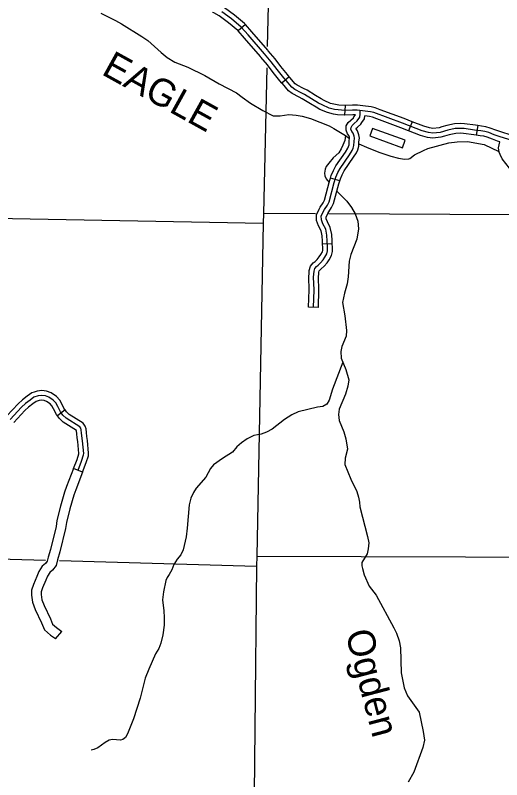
# Model space of a CAD drawing. Extents: x 0 to 3171, y 0 to 2059.
# Drawn here: x 1872.3 to 1997.6, y 790.8 to 987.9 of the extents above; entities that cross this region are included whole.
import ezdxf

# ---------------------------------------------------------------- set-up
doc = ezdxf.new("R2010")
doc.units = 0
for name, color, linetype in [('Level 35', 7, 'Continuous'), ('Level 4', 7, 'Continuous'), ('Level 45', 7, 'Continuous'), ('Level 46', 7, 'Continuous'), ('Level 5', 7, 'Continuous'), ('Level 57', 7, 'Continuous')]:
    doc.layers.add(name, color=color, linetype=linetype)

msp = doc.modelspace()

# ---------------------------------------------------------------- linework, layer by layer
at = {"layer": 'Level 35'}
for points in [[(1894.33, 988.4), (1896.9, 987.1), (1898.11, 986.49), (1899.61, 985.66), (1904.88, 982.36), (1906.38, 981.32), (1909.83, 978.25), (1911.4, 976.96), (1913.33, 975.73), (1916.74, 974.52), (1921.1, 972.37), (1924.81, 970.17), (1929.25, 967.85), (1930.73, 966.74), (1932.84, 965.18), (1936.01, 963.35), (1938.72, 961.93), (1940.55, 961.96), (1942.77, 962.31), (1944.67, 962.11), (1946.15, 961.83), (1948.35, 961.25), (1953.12, 959.36), (1954.34, 958.66), (1957.38, 956.88), (1958.4, 956.13)], [(1957.38, 956.88), (1957.2, 955.6), (1956.69, 954.35), (1956.25, 953.43), (1955.6, 952.43), (1954.12, 951.11), (1953.04, 949.77), (1952.4, 948.89), (1952.08, 948.21), (1951.91, 947.2), (1952, 946.51), (1952.38, 945.68), (1953.16, 944.74)], [(1960.78, 954.74), (1962.74, 953.85), (1965.9, 952.59), (1969.05, 951.58), (1971, 951.03), (1972.57, 950.73), (1973.63, 950.81)], [(1973.63, 950.81), (1973.9, 950.98), (1975.08, 951.9), (1977.46, 953.01), (1978.54, 953.5), (1983.96, 954.95), (1986.13, 955.25), (1988.75, 955.31), (1993.08, 954.52), (1996.88, 952.73)], [(1955.15, 942.53), (1957.71, 939.96), (1958.9, 938.3), (1959.8, 936.7), (1960.48, 934.79), (1960.67, 932.8), (1960.29, 930.18), (1958.74, 926.2), (1958.32, 924.5), (1958.04, 920.47), (1957.77, 918.6), (1957.11, 916.21), (1956.59, 913.78), (1957.17, 910.4), (1957.62, 906.63), (1957.47, 905.18), (1956.43, 902.51), (1956.15, 901.21), (1956.24, 899.44), (1957.44, 896.53), (1958.21, 893.89), (1957.95, 892.24), (1957.31, 890.21), (1955.72, 886.35)], [(1956.62, 898.45), (1954.01, 891.45), (1953.16, 888.61), (1952.51, 887.65), (1951.48, 887.05), (1950.12, 886.82), (1945.17, 885.61), (1943.51, 884.9), (1941.64, 883.68), (1938.49, 881.2), (1937.02, 880.44), (1935.58, 879.92), (1933.76, 879.56), (1931.98, 878.67), (1930.51, 877.64), (1929.35, 876.59), (1928.25, 875.27)], [(1955.72, 886.35), (1955.54, 884.96), (1955.74, 883.41), (1956.91, 880.51), (1957.42, 878.71), (1957.85, 875.98)], [(1928.25, 875.27), (1925.64, 873.6), (1923.3, 871.96), (1922.58, 871.05), (1921.36, 868.81), (1918.88, 865.96), (1918.16, 864.81), (1917.51, 863.35), (1917.07, 861.66), (1916.56, 855.66), (1916.29, 853.39), (1915.53, 850.1), (1914.89, 848.82), (1913.99, 847.65), (1913.09, 846.27), (1912.56, 844.9), (1911.92, 843.68), (1911.38, 842.97), (1911.03, 842.13), (1910.43, 839.21), (1910.18, 837.17), (1910.55, 834.34), (1910.66, 832.66), (1910.63, 830.61), (1910.25, 828.17), (1909.75, 826), (1909.29, 824.6), (1908.4, 823.22), (1906.64, 819.27), (1905.75, 816.96), (1904.44, 811.86), (1902.72, 806.55), (1901.17, 802.65), (1900.63, 801.71), (1899.97, 801.15), (1899.41, 801.01), (1897.3, 801.16), (1896.48, 801.03), (1895.43, 800.42), (1893.53, 799.05), (1892.54, 798.61), (1891.86, 798.44)], [(1957.85, 875.98), (1957.24, 873.71), (1957.2, 872.09), (1958.74, 868.3), (1960.25, 865.14), (1960.7, 863.66), (1960.98, 862.34), (1961.06, 861.13), (1963.04, 853.51), (1963.33, 851.87), (1963.21, 850.33), (1962.91, 849.03), (1961.55, 846.78), (1961.55, 845.95), (1961.69, 845.23), (1962.17, 843.62), (1963.44, 840.73), (1965.25, 838.35), (1969.8, 830), (1970.5, 828.59), (1971.2, 826.65), (1971.48, 824.82), (1971.65, 818.35), (1972.44, 814.52), (1973.29, 812.42), (1976.31, 808.2), (1977.39, 803.26), (1977.73, 801.03), (1977.28, 799.12), (1974.94, 792.73), (1973.46, 790.22)]]:
    msp.add_lwpolyline(points, dxfattribs=at)
at = {"layer": 'Level 4'}
for points in [[(1940.08, 1108.86), (1938.25, 1024.59), (1938.2, 1022.15), (1937.2, 979.77)], [(1937.07, 974.28), (1936.19, 936.73), (1936.13, 934.31), (1934.5, 848.41), (1934.45, 845.84), (1933.54, 762.01), (1933.51, 759.63), (1932.18, 672.84), (1931.53, 633.35)]]:
    msp.add_lwpolyline(points, dxfattribs=at)
at = {"layer": 'Level 45'}
for p, q in [((1931.54, 985.49), (1929.66, 983.84)), ((1942.85, 972), (1940.96, 970.37)), ((1957.24, 964.58), (1957.07, 962.08)), ((1974.51, 960.42), (1973.61, 958.09)), ((1991.39, 959.43), (1990.99, 956.96)), ((1955.88, 945.17), (1953.49, 945.88)), ((1953.92, 928.98), (1951.42, 928.87)), ((1950.35, 912.51), (1947.85, 912.59)), ((1885.09, 886.14), (1883.13, 884.59)), ((1889.6, 870.12), (1887.27, 871.04))]:
    msp.add_line(p, q, dxfattribs=at)
for points in [[(1931.54, 985.49), (1931.35, 985.7), (1928.77, 987.9), (1926.16, 989.76), (1924.48, 990.76), (1923.86, 990.96)], [(1929.66, 983.84), (1929.6, 983.91), (1927.23, 985.92), (1924.79, 987.67), (1923.45, 988.47), (1923.11, 988.58)], [(2001.9, 955.03), (1996.93, 956.59), (1995.65, 957.08), (1994.25, 957.61), (1993.27, 957.88), (1992.19, 958.03), (1990.61, 958.28), (1987.91, 958.63), (1986.86, 958.71), (1985.58, 958.63), (1983.74, 958.23), (1981.69, 957.64), (1979.83, 957.46), (1978.73, 957.61), (1977.1, 958.08), (1972.01, 960.04), (1964.62, 962.8), (1963.74, 963.01), (1961.69, 963.25), (1960.34, 963.42), (1959.18, 963.43), (1957.2, 963.33), (1955.45, 963.45), (1954.5, 963.6), (1953.09, 963.95), (1951.31, 964.73), (1950.41, 965.23), (1946.81, 967.43), (1945.95, 967.88), (1944.27, 968.74), (1943.49, 969.29), (1942.03, 971.04), (1941.42, 971.75), (1939.72, 973.9), (1938.23, 975.88), (1936.5, 977.9), (1932.23, 982.81), (1930.48, 984.8), (1928, 986.91), (1925.48, 988.71)], [(1937.33, 978.86), (1933.17, 983.63), (1931.54, 985.49)], [(1935.44, 977.22), (1931.29, 981.98), (1929.66, 983.84)], [(1942.85, 972), (1942.38, 972.55), (1940.71, 974.67), (1939.21, 976.66), (1937.45, 978.71), (1937.33, 978.86)], [(1940.96, 970.37), (1940.45, 970.96), (1938.73, 973.14), (1937.26, 975.1), (1935.56, 977.08), (1935.44, 977.22)], [(1949.6, 967.18), (1947.43, 968.51), (1946.52, 968.99), (1944.92, 969.81), (1944.35, 970.21), (1942.98, 971.85), (1942.85, 972)], [(1948.3, 965.05), (1946.19, 966.34), (1945.37, 966.77), (1943.62, 967.66), (1942.64, 968.36), (1941.07, 970.23), (1940.96, 970.37)], [(1957.24, 964.58), (1955.59, 964.7), (1954.75, 964.83), (1953.5, 965.14), (1951.86, 965.85), (1951.04, 966.31), (1949.6, 967.18)], [(1957.07, 962.08), (1955.31, 962.21), (1954.25, 962.38), (1952.69, 962.77), (1950.76, 963.6), (1949.78, 964.15), (1948.3, 965.05)], [(1966.26, 963.52), (1964.98, 964), (1963.96, 964.24), (1961.84, 964.49), (1960.42, 964.67), (1959.15, 964.68), (1957.22, 964.58), (1957.24, 964.58)], [(1974.51, 960.42), (1972.45, 961.21), (1966.26, 963.52)], [(1949.1, 912.55), (1949.26, 917.12), (1949.13, 920.37), (1949.23, 921.87), (1949.43, 922.6), (1949.86, 923.1), (1950.31, 923.45), (1950.93, 924.03), (1951.58, 924.8), (1952.03, 925.5), (1952.56, 926.38), (1952.74, 927.11), (1952.71, 928.03), (1952.64, 929.66), (1952.54, 931.18), (1952.24, 932.71), (1951.53, 934.12), (1951.13, 935.17), (1951.11, 936.12), (1951.93, 937.77), (1952.69, 938.93), (1953.11, 939.78), (1954.45, 944.74), (1954.85, 946.1), (1955.37, 947.31), (1955.96, 948.4), (1958.4, 951.92), (1959.05, 952.97), (1959.32, 953.6), (1959.5, 954.27), (1959.56, 955.36), (1959.66, 956.18), (1959.58, 956.71), (1959.3, 957.48), (1958.98, 957.93), (1958.75, 958.46), (1958.77, 958.96), (1959.05, 959.44), (1959.6, 959.92), (1960.31, 960.61), (1961.03, 961.6), (1961.13, 962.37), (1961.13, 963.3)], [(1959.9, 962.17), (1959.21, 962.18), (1957.19, 962.08), (1957.07, 962.08)], [(1957.96, 953.59), (1958.14, 954.01), (1958.26, 954.47), (1958.32, 955.48), (1958.4, 956.15), (1958.36, 956.4), (1958.18, 956.9), (1957.89, 957.31), (1957.49, 958.23), (1957.54, 959.32), (1958.07, 960.24), (1958.75, 960.84), (1959.37, 961.43), (1959.52, 961.64)], [(1959.52, 961.64), (1959.9, 962.17)], [(1961.54, 960.18), (1962.23, 961.13), (1962.33, 961.92)], [(1965.38, 961.18), (1964.26, 961.6), (1963.53, 961.78), (1962.33, 961.92)], [(1960.24, 952.58), (1960.51, 953.19), (1960.74, 954.08), (1960.81, 955.25), (1960.93, 956.21), (1960.79, 957.03), (1960.42, 958.07), (1960.08, 958.55), (1960.04, 958.64), (1960.45, 959), (1961.26, 959.79), (1961.54, 960.18)], [(1973.61, 958.09), (1971.56, 958.87), (1965.38, 961.18)], [(1982.17, 959.08), (1981.45, 958.87), (1979.85, 958.71), (1978.99, 958.83), (1977.5, 959.27), (1974.51, 960.42)], [(1991.39, 959.43), (1990.79, 959.52), (1988.03, 959.88), (1986.86, 959.96), (1985.41, 959.88), (1983.43, 959.45), (1982.17, 959.08)], [(1982.87, 956.68), (1981.92, 956.4), (1979.8, 956.2), (1978.46, 956.38), (1976.7, 956.9), (1973.61, 958.09)], [(1999.99, 956.94), (1997.34, 957.77), (1996.1, 958.25), (1994.64, 958.8), (1993.53, 959.11), (1992.38, 959.27), (1991.39, 959.43)], [(1990.99, 956.96), (1990.44, 957.05), (1987.78, 957.39), (1986.85, 957.46), (1985.75, 957.39), (1984.04, 957.02), (1982.87, 956.68)], [(1997.11, 955.22), (1996.51, 955.41), (1995.21, 955.91), (1993.86, 956.42), (1993.01, 956.66), (1992.01, 956.8), (1990.99, 956.96)], [(2000.5, 947.28), (1997.72, 950.86), (1997.16, 951.97), (1996.93, 952.59), (1996.79, 953.69), (1997.11, 955.22)], [(1953.49, 945.88), (1953.68, 946.52), (1954.24, 947.85), (1954.89, 949.05), (1957.35, 952.61), (1957.94, 953.56), (1957.96, 953.59)], [(1955.88, 945.17), (1956.03, 945.67), (1956.5, 946.76), (1957.03, 947.74), (1959.44, 951.24), (1960.16, 952.39), (1960.24, 952.58)], [(1950.59, 937.87), (1950.85, 938.39), (1951.6, 939.55), (1951.94, 940.22), (1953.25, 945.08), (1953.49, 945.88)], [(1952.82, 936.75), (1953.02, 937.15), (1953.77, 938.3), (1954.29, 939.33), (1955.66, 944.4), (1955.88, 945.17)], [(1951.42, 928.87), (1951.39, 929.59), (1951.29, 931.02), (1951.04, 932.31), (1950.39, 933.61), (1949.89, 934.92), (1949.85, 936.4), (1950.59, 937.87)], [(1953.92, 928.98), (1953.88, 929.73), (1953.78, 931.35), (1953.43, 933.12), (1952.68, 934.62), (1952.38, 935.41), (1952.37, 935.84), (1952.82, 936.75)], [(1947.95, 921.43), (1947.99, 922.08), (1948.3, 923.2), (1948.99, 924.01), (1949.5, 924.41), (1950.03, 924.89), (1950.58, 925.55), (1950.97, 926.16), (1951.39, 926.86), (1951.48, 927.24), (1951.46, 927.98), (1951.42, 928.87)], [(1950.44, 921.26), (1950.47, 921.66), (1950.56, 922), (1950.72, 922.19), (1951.11, 922.5), (1951.84, 923.16), (1952.59, 924.06), (1953.1, 924.84), (1953.73, 925.9), (1953.99, 926.97), (1953.96, 928.07), (1953.92, 928.98)], [(1947.85, 912.59), (1948.01, 917.12), (1947.88, 920.38), (1947.95, 921.43)], [(1950.35, 912.51), (1950.51, 917.12), (1950.38, 920.35), (1950.44, 921.26)], [(1877.15, 890.75), (1876.51, 890.55), (1875.32, 889.68), (1874.11, 888.76), (1872.97, 887.74), (1870.08, 884.57)], [(1885.09, 886.14), (1884.98, 886.28), (1884.35, 887.54), (1883.78, 888.67), (1882.85, 889.62), (1881.51, 890.51), (1880.33, 890.98), (1879.08, 891.14), (1877.91, 890.98), (1877.15, 890.75)], [(1889.88, 874.56), (1889.91, 874.94), (1889.61, 878.14), (1889.37, 880.15), (1889.27, 880.98), (1889.14, 881.4), (1888.87, 881.76), (1885.4, 884), (1884.55, 884.8), (1883.91, 885.61), (1883.24, 886.98), (1882.75, 887.94), (1882.05, 888.66), (1880.93, 889.4), (1880.02, 889.76), (1879.09, 889.88), (1878.18, 889.75), (1877.08, 889.42), (1876.06, 888.68), (1874.91, 887.8), (1873.85, 886.85), (1870.91, 883.63)], [(1877.87, 888.35), (1877.64, 888.28), (1876.81, 887.68), (1875.71, 886.83), (1874.74, 885.96), (1871.93, 882.89)], [(1883.13, 884.59), (1882.85, 884.94), (1882.12, 886.42), (1881.72, 887.2), (1881.25, 887.69), (1880.35, 888.28), (1879.7, 888.54), (1879.1, 888.62), (1878.44, 888.53), (1877.87, 888.35)], [(1890.74, 879.25), (1890.61, 880.29), (1890.5, 881.23), (1890.28, 881.98), (1889.73, 882.69), (1886.17, 884.98), (1885.48, 885.65), (1885.09, 886.14)], [(1888.25, 878.95), (1888.13, 880), (1888.04, 880.72), (1888.01, 880.82), (1888.01, 880.83), (1884.62, 883.01), (1883.62, 883.96), (1883.13, 884.59)], [(1887.27, 871.04), (1888.2, 873.38), (1888.65, 874.8), (1888.66, 874.93), (1888.37, 878.01), (1888.25, 878.95)], [(1889.6, 870.12), (1890.55, 872.54), (1891.12, 874.32), (1891.17, 874.95), (1890.85, 878.27), (1890.74, 879.25)], [(1888.44, 870.58), (1889.37, 872.96), (1889.88, 874.56)]]:
    msp.add_lwpolyline(points, dxfattribs=at)
at = {"layer": 'Level 46'}
for points in [[(1887.27, 871.04), (1885.48, 866.4), (1884.97, 864.95), (1883.91, 861.29), (1883.01, 857.6), (1882.78, 856.05), (1881.34, 850.18), (1880.78, 848.16), (1880.48, 847.16), (1880.03, 846.57), (1879.21, 845.86), (1878.35, 844.45), (1877.83, 843.19), (1876.98, 841.16), (1876.43, 839.66), (1876.41, 838.38), (1876.7, 836.55), (1877.4, 834.73), (1879.03, 831.27), (1879.76, 829.44), (1881.32, 828.11), (1882.34, 827.35), (1882.65, 827.09), (1884.28, 828.98)], [(1889.6, 870.12), (1887.83, 865.53), (1887.35, 864.18), (1886.32, 860.65), (1885.47, 857.12), (1885.24, 855.56), (1883.76, 849.55), (1883.18, 847.48), (1882.76, 846.02), (1881.86, 844.84), (1881.14, 844.22), (1880.59, 843.32), (1880.13, 842.23), (1879.31, 840.25), (1878.93, 839.2), (1878.91, 838.55), (1879.13, 837.2), (1879.7, 835.71), (1881.32, 832.27), (1881.85, 830.94), (1882.88, 830.07), (1883.9, 829.31), (1884.28, 828.98)]]:
    msp.add_lwpolyline(points, dxfattribs=at)
at = {"layer": 'Level 5'}
for points in [[(1949.6, 936.66), (1936.19, 936.73)], [(1999.86, 936.42), (1953.06, 936.65)], [(1848.38, 935.93), (1936.13, 934.31)], [(1846.68, 848.36), (1880.02, 847.4)], [(1883.64, 847.3), (1934.45, 845.84)], [(1934.5, 848.41), (2015.16, 848.18), (2025.81, 848.3)]]:
    msp.add_lwpolyline(points, dxfattribs=at)
at = {"layer": 'Level 57'}
for p, q in [((1964.33, 958.71), (1963.61, 956.76)), ((1972.74, 955.63), (1964.33, 958.71)), ((1963.61, 956.76), (1972.02, 953.67)), ((1972.02, 953.67), (1972.74, 955.63))]:
    msp.add_line(p, q, dxfattribs=at)

# ---------------------------------------------------------------- texts
at = {"layer": 'Level 35'}
for s, rotation, p in [('EAGLE', 331.0504, (1894.22, 972.76)), ('Ogden', 284.6945, (1957.27, 828.65))]:
    msp.add_text(s, height=7.04, rotation=rotation, dxfattribs=at).set_placement(p)

doc.saveas('drawing.dxf')
